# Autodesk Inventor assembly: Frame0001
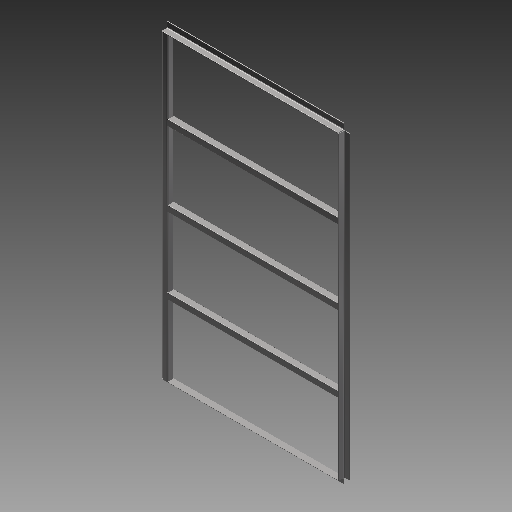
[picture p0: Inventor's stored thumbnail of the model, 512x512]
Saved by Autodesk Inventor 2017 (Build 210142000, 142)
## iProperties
Created: 2020-07
Part Number: Frame0001
Document SubType Name: Assembly
Designer: X
Mass: 25984.5 g
Surface Area: 21556.8 cm^2
Volume: 3310.13 cm^3
Density: 7.85 g/cm^3
_FrameDoc: Frame Assembly
_Version: 15.0.0
Author: X
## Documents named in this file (16)
- C:\Users\WindowsX\Desktop\brama\skrzydlo_lewe\Frame\Frame0001.iam
- C:\Users\WindowsX\Desktop\brama\skrzydlo_lewe\Frame\Skeleton0001.ipt
- C:\Users\WindowsX\Desktop\brama\skrzydlo_lewe\Frame\PN L40x40x4 00000011.ipt
- PN L35x35x4 00000004.ipt
- C:\Users\WindowsX\Desktop\brama\skrzydlo_lewe\Frame\PN L40x40x4 00000012.ipt
- PN L35x35x4 00000002.ipt
- C:\Users\WindowsX\Desktop\brama\skrzydlo_lewe\Frame\PN L40x40x4 00000013.ipt
- PN L35x35x4 00000003.ipt
- C:\Users\WindowsX\Desktop\brama\skrzydlo_lewe\Frame\PN 40 x 40 x 2 00000016.ipt
- PN 35 x 35 x 2 00000008.ipt
- C:\Users\WindowsX\Desktop\brama\skrzydlo_lewe\Frame\PN 40 x 40 x 2 00000017.ipt
- PN 35 x 35 x 2 00000009.ipt
- C:\Users\WindowsX\Desktop\brama\skrzydlo_lewe\Frame\PN 40 x 40 x 4 00000018.ipt
- PN 40 x 40 x 4 00000018.ipt
- C:\Users\WindowsX\Desktop\brama\skrzydlo_lewe\Frame\PN 40 x 40 x 2 00000019.ipt
- PN 35 x 35 x 2 00000010.ipt
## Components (8 placed, 8 different names)
1. Model odniesienia ramy
2. PN L40x40x4 00000012:1
3. PN L40x40x4 00000013:1
4. PN L40x40x4 00000011:1
5. PN 40 x 40 x 2 00000016:1
6. PN 40 x 40 x 2 00000017:1
7. PN 40 x 40 x 2 00000019:1
8. PN 40 x 40 x 4 00000018:1
